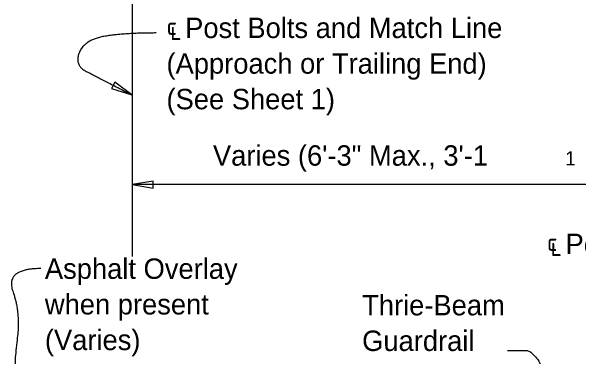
# Model space of a CAD drawing. Extents: x 21526.6 to 21595.9, y 56117 to 56157.3.
# Drawn here: x 21527.25 to 21532.85, y 56138.93 to 56142.34 of the extents above; entities that cross this region are included whole.
import ezdxf

# ---------------------------------------------------------------- set-up
doc = ezdxf.new("R2010")
doc.units = 0
for name, color, linetype in [('Border', 7, 'Continuous'), ('Patterning', 7, 'Continuous'), ('PlotBorder_dp', 7, 'Continuous')]:
    doc.layers.add(name, color=color, linetype=linetype)

msp = doc.modelspace()

# ---------------------------------------------------------------- linework, layer by layer
at = {"layer": 'Patterning'}
msp.add_line((21528.4455, 56142.6776), (21528.4455, 56139.9183), dxfattribs=at)
at = {"layer": 'PlotBorder_dp'}
msp.add_line((21539.9741, 56140.6266), (21528.4455, 56140.6266), dxfattribs=at)
for points in [[(21528.4441, 56141.5129), (21528.2756, 56141.6403), (21528.2431, 56141.5777)], [(21528.4455, 56140.6266), (21528.6538, 56140.5913), (21528.6538, 56140.6618)]]:
    msp.add_lwpolyline(points, close=True, dxfattribs=at)
for points in [[(21528.682, 56142.1252), (21528.3692, 56142.1252), (21527.9772, 56142.0591), (21527.8715, 56141.8081), (21528.1138, 56141.6847), (21528.4441, 56141.5129)], [(21527.5433, 56139.7972), (21527.186, 56139.7968), (21527.352, 56139.3409), (21527.253, 56138.6974), (21527.5005, 56137.7639), (21527.5005, 56134.6471)], [(21532.1515, 56138.9888), (21532.2823, 56138.9888), (21532.3882, 56138.9888), (21532.5399, 56138.7618), (21532.2472, 56137.5615), (21532.1507, 56137.1892)]]:
    msp.add_open_spline(points, degree=2, dxfattribs=at)

# ---------------------------------------------------------------- texts
at = {"layer": 'Border'}
for s, height, p in [('Varies (6\'-3" Max., 3\'-1', 0.2016, (21529.2435, 56140.814)), ('1', 0.1411, (21532.7206, 56140.816)), ('℄ Post', 0.2016, (21532.5404, 56139.9408))]:
    msp.add_text(s, height=height, dxfattribs=at).set_placement(p)
at = {"layer": 'PlotBorder_dp'}
for s, p in [('℄ Post Bolts and Match Line', (21528.785, 56142.0753)), ('(Approach or Trailing End)', (21528.785, 56141.7233)), ('(See Sheet 1)', (21528.785, 56141.3713)), ('Asphalt Overlay', (21527.5844, 56139.6959)), ('when present', (21527.5844, 56139.3439)), ('Thrie-Beam ', (21530.7165, 56139.3351)), ('(Varies)', (21527.5844, 56138.9919)), ('Guardrail', (21530.7165, 56138.9831))]:
    msp.add_text(s, height=0.2016, dxfattribs=at).set_placement(p)

doc.saveas('drawing.dxf')
